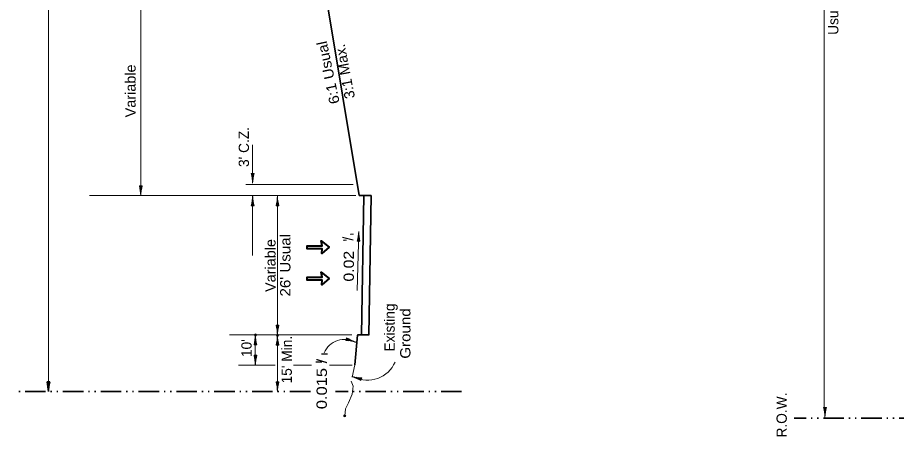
# Model space of a CAD drawing. Extents: x 2363427 to 2368559, y 6957299 to 6980140.
# Drawn here: x 2364654 to 2365851, y 6958010 to 6958581 of the extents above; entities that cross this region are included whole.
import ezdxf
from ezdxf.enums import TextEntityAlignment as Align

# ---------------------------------------------------------------- set-up
doc = ezdxf.new("R2010")
doc.units = 0
doc.header["$LTSCALE"] = 5.6
doc.header["$PDMODE"] = 32
doc.header["$PDSIZE"] = 2.8
doc.linetypes.add('DASH_DOUBLE_DOT', pattern=[9.2, 5, -1.2, 0.3, -1.2, 0.3, -1.2])
doc.linetypes.add('MEDIUM_DASHED', pattern=[4.5, 3, -1.5])
for name, color, linetype, lineweight in [('1', 7, 'Continuous', 13), ('3', 7, 'Continuous', 35), ('4', 7, 'Continuous', 13), ('40', 7, 'Continuous', 35), ('48', 7, 'Continuous', 25), ('6', 7, 'Continuous', 13), ('8', 7, 'Continuous', 13)]:
    doc.layers.add(name, color=color, linetype=linetype, lineweight=lineweight)

msp = doc.modelspace()

# ---------------------------------------------------------------- linework, layer by layer
at = {"layer": '1'}
for p, q in [((2365122.006, 6958088.321), (2365109.964, 6958091.909)), ((2365121.864, 6958087.843), (2365113.612, 6958090.301)), ((2365122.149, 6958088.801), (2365115.105, 6958090.899)), ((2365121.72, 6958087.363), (2365117.061, 6958088.751)), ((2365122.292, 6958089.28), (2365118.193, 6958090.501)), ((2365121.578, 6958086.884), (2365119.296, 6958087.564)), ((2365122.434, 6958089.759), (2365120.916, 6958090.211)), ((2365122.534, 6958090.095), (2365121.441, 6958086.424))]:
    msp.add_line(p, q, dxfattribs=at)
at = {"layer": '1', "linetype": 'MEDIUM_DASHED'}
msp.add_lwpolyline([(2365112.979, 6958107.766), (2365108.239, 6958085.654), (2365110.767, 6958078.9), (2365109.503, 6958068.094), (2365104.447, 6958055.936), (2365100.655, 6958047.83), (2365099.391, 6958038.374)], dxfattribs=at)
at = {"layer": '1'}
for centre, radius, start, end in [((2365130.612, 6958127.466), 40.455, 242.99828, 337.03823), ((2365085.206, 6958023.96), 72.212, 59.88222, 70.56827), ((2365126.387, 6958162.204), 72.212, 256.25538, 266.94143)]:
    msp.add_arc(centre, radius, start, end, dxfattribs=at)
msp.add_point((2365099.391, 6958038.374), dxfattribs=at)
at = {"layer": '3'}
for p, q in [((2365055.653, 6958721.475), (2365118.982, 6958338.693)), ((2365118.982, 6958338.693), (2365125.574, 6958338.663)), ((2365125.574, 6958338.663), (2365122.253, 6958148.629)), ((2365125.574, 6958338.663), (2365135.576, 6958338.755)), ((2365135.574, 6958338.622), (2365132.252, 6958148.542)), ((2365116.835, 6958148.531), (2365112.979, 6958107.766)), ((2365132.254, 6958148.629), (2365116.836, 6958148.629))]:
    msp.add_line(p, q, dxfattribs=at)
at = {"layer": '3', "lineweight": 13}
for p, q in [((2365110.704, 6958353.693), (2364964.692, 6958353.693)), ((2365114.719, 6958338.693), (2364751.658, 6958338.693)), ((2365116.266, 6958209.329), (2365118.542, 6958289.583)), ((2365117.23, 6958276.303), (2365117.368, 6958281.163)), ((2365117.73, 6958276.289), (2365117.974, 6958284.895)), ((2365118.229, 6958276.275), (2365118.586, 6958288.833)), ((2365118.729, 6958276.261), (2365118.938, 6958283.607)), ((2365119.229, 6958276.245), (2365119.35, 6958280.521)), ((2365120.078, 6958276.221), (2365116.25, 6958276.331)), ((2365116.73, 6958276.317), (2365116.798, 6958278.697)), ((2365119.728, 6958276.231), (2365119.774, 6958277.817)), ((2365109.097, 6958148.693), (2364942.34, 6958148.693)), ((2365116.835, 6958148.531), (2365116.836, 6958148.629))]:
    msp.add_line(p, q, dxfattribs=at)
at = {"layer": '3', "linetype": 'DASH_DOUBLE_DOT'}
for p, q in [((2365052.774, 6958071.447), (2364653.955, 6958071.447)), ((2365258.568, 6958071.447), (2365086.792, 6958071.447))]:
    msp.add_line(p, q, dxfattribs=at)
msp.add_lwpolyline([(2366112.816, 6958035.448), (2366088.198, 6958035.448), (2365711.269, 6958035.448)], dxfattribs=at)
at = {"layer": '3', "lineweight": 13}
for centre, start, end in [((2365046.548, 6958295.207), 344.84626, 355.53231), ((2365190.738, 6958291.119), 181.21943, 191.90548)]:
    msp.add_arc(centre, 72.212, start, end, dxfattribs=at)
at = {"layer": '4'}
for p, q in [((2365752.334, 6958047.045), (2365752.334, 6959081.469)), ((2364977.895, 6958135.176), (2364977.895, 6958147.74)), ((2364977.895, 6958135.176), (2364977.895, 6958147.74)), ((2364976.395, 6958135.176), (2364976.395, 6958137.558)), ((2364976.395, 6958135.176), (2364976.395, 6958137.558)), ((2364976.895, 6958135.176), (2364976.895, 6958140.038)), ((2364976.895, 6958135.176), (2364976.895, 6958140.038)), ((2364977.395, 6958135.176), (2364977.395, 6958143.786)), ((2364977.395, 6958135.176), (2364977.395, 6958143.786)), ((2364978.395, 6958135.176), (2364978.395, 6958142.526)), ((2364978.395, 6958135.176), (2364978.395, 6958142.526)), ((2364978.895, 6958135.176), (2364978.895, 6958139.453)), ((2364978.895, 6958135.176), (2364978.895, 6958139.453)), ((2364979.395, 6958135.176), (2364979.395, 6958136.762)), ((2364979.395, 6958135.176), (2364979.395, 6958136.762)), ((2365100.761, 6958141.274), (2365101.926, 6958144.923)), ((2365100.868, 6958141.607), (2365102.378, 6958141.125)), ((2365101.02, 6958142.084), (2365105.094, 6958140.783)), ((2365101.172, 6958142.56), (2365108.173, 6958140.323)), ((2365101.324, 6958143.037), (2365113.292, 6958139.213)), ((2365101.476, 6958143.513), (2365109.678, 6958140.893)), ((2365101.628, 6958143.989), (2365106.26, 6958142.509)), ((2365101.78, 6958144.465), (2365104.049, 6958143.741)), ((2364979.745, 6958135.176), (2364975.915, 6958135.176)), ((2364979.745, 6958135.176), (2364975.915, 6958135.176)), ((2364975.936, 6958120.983), (2364979.766, 6958120.983)), ((2364975.936, 6958120.983), (2364979.766, 6958120.983)), ((2364976.286, 6958120.983), (2364976.286, 6958119.399)), ((2364976.286, 6958120.983), (2364976.286, 6958119.399)), ((2364976.786, 6958120.983), (2364976.786, 6958116.707)), ((2364976.786, 6958120.983), (2364976.786, 6958116.707)), ((2364977.286, 6958120.983), (2364977.286, 6958113.633)), ((2364977.286, 6958120.983), (2364977.286, 6958113.633)), ((2364977.786, 6958120.983), (2364977.786, 6958108.419)), ((2364977.786, 6958120.983), (2364977.786, 6958108.419)), ((2364978.286, 6958120.983), (2364978.286, 6958112.374)), ((2364978.286, 6958120.983), (2364978.286, 6958112.374)), ((2364978.786, 6958120.983), (2364978.786, 6958116.121)), ((2364978.786, 6958120.983), (2364978.786, 6958116.121)), ((2364979.286, 6958120.983), (2364979.286, 6958118.602)), ((2364979.286, 6958120.983), (2364979.286, 6958118.602)), ((2365004.525, 6958107.585), (2364954.893, 6958107.585)), ((2365054.133, 6958107.585), (2365029.75, 6958107.585)), ((2365109.628, 6958107.585), (2365078.517, 6958107.585)), ((2365751.332, 6958049.826), (2365755.162, 6958049.826)), ((2365751.682, 6958049.826), (2365751.682, 6958048.241)), ((2365752.182, 6958049.826), (2365752.182, 6958045.549)), ((2365752.682, 6958049.826), (2365752.682, 6958042.476)), ((2365753.182, 6958049.826), (2365753.182, 6958037.262)), ((2365753.682, 6958049.826), (2365753.682, 6958041.217)), ((2365754.182, 6958049.826), (2365754.182, 6958044.964)), ((2365754.682, 6958049.826), (2365754.682, 6958047.445))]:
    msp.add_line(p, q, dxfattribs=at)
at = {"layer": '4', "lineweight": 25}
for p, q in [((2365068.431, 6958111.524), (2365060.271, 6958111.524)), ((2365075.749, 6958122.347), (2365067.588, 6958122.347))]:
    msp.add_line(p, q, dxfattribs=at)
at = {"layer": '4', "lineweight": 35}
for p, q in [((2364694.018, 6958084.759), (2364697.848, 6958084.759)), ((2364694.368, 6958084.759), (2364694.368, 6958083.173)), ((2364694.868, 6958084.759), (2364694.868, 6958080.481)), ((2364695.368, 6958084.759), (2364695.368, 6958077.409)), ((2364695.868, 6958084.759), (2364695.868, 6958072.195)), ((2364696.368, 6958084.759), (2364696.368, 6958076.149)), ((2364696.868, 6958084.759), (2364696.868, 6958079.897)), ((2364697.368, 6958084.759), (2364697.368, 6958082.377))]:
    msp.add_line(p, q, dxfattribs=at)
at = {"layer": '4'}
for centre, radius, start, end in [((2364905.707, 6958152.069), 72.212, 346.47039, 357.15644), ((2364905.707, 6958152.069), 72.212, 346.47039, 357.15644), ((2365049.954, 6958152.069), 72.212, 182.84356, 193.52961), ((2365049.954, 6958152.069), 72.212, 182.84356, 193.52961), ((2365099.004, 6958112.983), 29.635, 59.62074, 157.81619), ((2365095.488, 6958069.253), 72.212, 75.12659, 85.81264), ((2365139.385, 6958206.658), 72.212, 238.75343, 249.43948), ((2364905.728, 6958104.088), 72.212, 2.84356, 13.52961), ((2364905.728, 6958104.088), 72.212, 2.84356, 13.52961), ((2365049.975, 6958104.088), 72.212, 166.47039, 177.15644), ((2365049.975, 6958104.088), 72.212, 166.47039, 177.15644), ((2365681.124, 6958032.932), 72.212, 2.84356, 13.52961), ((2365825.371, 6958032.932), 72.212, 166.47039, 177.15644)]:
    msp.add_arc(centre, radius, start, end, dxfattribs=at)
at = {"layer": '4', "lineweight": 35}
for centre, start, end in [((2364623.81, 6958067.864), 2.84356, 13.52961), ((2364768.057, 6958067.864), 166.47039, 177.15644)]:
    msp.add_arc(centre, 72.212, start, end, dxfattribs=at)
at = {"layer": '4'}
for p in [(2364977.831, 6958148.889), (2364977.831, 6958148.488)]:
    msp.add_point(p, dxfattribs=at)
at = {"layer": '40'}
for p, q in [((2365068.578, 6958266.155), (2365048.073, 6958265.959)), ((2365068.578, 6958223.336), (2365048.073, 6958223.141))]:
    msp.add_line(p, q, dxfattribs=at)
for points in [[(2365068.54, 6958270.249), (2365048.036, 6958270.055), (2365048.073, 6958265.959)], [(2365068.578, 6958266.155), (2365068.046, 6958259.839), (2365078.433, 6958268.375), (2365067.333, 6958276.977), (2365068.54, 6958270.249)], [(2365068.578, 6958223.336), (2365068.046, 6958217.021), (2365078.433, 6958225.556), (2365067.333, 6958234.159), (2365068.54, 6958227.431)], [(2365068.54, 6958227.431), (2365048.036, 6958227.236), (2365048.073, 6958223.141)]]:
    msp.add_lwpolyline(points, dxfattribs=at)
at = {"layer": '48', "lineweight": 13}
msp.add_lwpolyline([(2365122.253, 6958148.629), (2365132.252, 6958148.542), (2365135.574, 6958338.622), (2365125.574, 6958338.663)], close=True, dxfattribs=at)
at = {"layer": '6'}
for p, q in [((2364695.934, 6958071.447), (2364695.934, 6959071.447)), ((2364821.74, 6958619.485), (2364821.74, 6958338.693)), ((2364973.994, 6958355.333), (2364973.994, 6958407.695)), ((2364972.08, 6958368.645), (2364975.91, 6958368.645)), ((2364972.43, 6958368.645), (2364972.43, 6958367.061)), ((2364972.93, 6958368.645), (2364972.93, 6958364.369)), ((2364973.43, 6958368.645), (2364973.43, 6958361.295)), ((2364973.93, 6958368.645), (2364973.93, 6958356.081)), ((2364974.43, 6958368.645), (2364974.43, 6958360.035)), ((2364974.93, 6958368.645), (2364974.93, 6958363.783)), ((2364975.43, 6958368.645), (2364975.43, 6958366.263)), ((2364819.825, 6958352.003), (2364823.655, 6958352.003)), ((2364820.175, 6958352.003), (2364820.175, 6958350.419)), ((2364820.675, 6958352.003), (2364820.675, 6958347.727)), ((2364821.175, 6958352.003), (2364821.175, 6958344.653)), ((2364821.675, 6958352.003), (2364821.675, 6958339.439)), ((2364822.175, 6958352.003), (2364822.175, 6958343.395)), ((2364822.675, 6958352.003), (2364822.675, 6958347.141)), ((2364823.175, 6958352.003), (2364823.175, 6958349.623)), ((2364972.56, 6958324.567), (2364972.56, 6958326.949)), ((2364973.06, 6958324.567), (2364973.06, 6958329.429)), ((2364973.56, 6958324.567), (2364973.56, 6958333.177)), ((2364973.994, 6958337.879), (2364973.994, 6958256.743)), ((2364974.06, 6958324.567), (2364974.06, 6958337.131)), ((2364974.56, 6958324.567), (2364974.56, 6958331.917)), ((2364975.06, 6958324.567), (2364975.06, 6958328.845)), ((2365006.396, 6958324.567), (2365006.396, 6958326.949)), ((2365006.896, 6958324.567), (2365006.896, 6958329.429)), ((2365007.396, 6958324.567), (2365007.396, 6958333.177)), ((2365007.83, 6958337.879), (2365007.83, 6958148.693)), ((2365007.896, 6958324.567), (2365007.896, 6958337.131)), ((2365008.396, 6958324.567), (2365008.396, 6958331.917)), ((2365008.896, 6958324.567), (2365008.896, 6958328.845)), ((2364975.91, 6958324.567), (2364972.08, 6958324.567)), ((2364975.56, 6958324.567), (2364975.56, 6958326.153)), ((2365009.746, 6958324.567), (2365005.916, 6958324.567)), ((2365009.396, 6958324.567), (2365009.396, 6958326.153)), ((2365005.916, 6958162.003), (2365009.746, 6958162.003)), ((2365006.266, 6958162.003), (2365006.266, 6958160.419)), ((2365006.766, 6958162.003), (2365006.766, 6958157.727)), ((2365007.266, 6958162.003), (2365007.266, 6958154.653)), ((2365007.766, 6958162.003), (2365007.766, 6958149.439)), ((2365008.266, 6958162.003), (2365008.266, 6958153.395)), ((2365008.766, 6958162.003), (2365008.766, 6958157.141)), ((2365009.266, 6958162.003), (2365009.266, 6958159.623)), ((2364977.56, 6958148.487), (2364977.56, 6958107.585)), ((2365007.83, 6958148.067), (2365007.83, 6958071.447)), ((2365006.396, 6958134.755), (2365006.396, 6958137.137)), ((2365006.896, 6958134.755), (2365006.896, 6958139.617)), ((2365007.396, 6958134.755), (2365007.396, 6958143.365)), ((2365007.896, 6958134.755), (2365007.896, 6958147.319)), ((2365008.396, 6958134.755), (2365008.396, 6958142.105)), ((2365008.896, 6958134.755), (2365008.896, 6958139.033)), ((2365009.396, 6958134.755), (2365009.396, 6958136.341)), ((2365009.746, 6958134.755), (2365005.916, 6958134.755)), ((2365005.916, 6958084.759), (2365009.746, 6958084.759)), ((2365006.266, 6958084.759), (2365006.266, 6958083.173)), ((2365006.766, 6958084.759), (2365006.766, 6958080.481)), ((2365007.266, 6958084.759), (2365007.266, 6958077.409)), ((2365007.766, 6958084.759), (2365007.766, 6958072.195)), ((2365008.266, 6958084.759), (2365008.266, 6958076.149)), ((2365008.766, 6958084.759), (2365008.766, 6958079.897)), ((2365009.266, 6958084.759), (2365009.266, 6958082.377))]:
    msp.add_line(p, q, dxfattribs=at)
for centre, start, end in [((2364901.871, 6958351.751), 2.84356, 13.52961), ((2365046.118, 6958351.751), 166.47039, 177.15644), ((2364749.616, 6958335.11), 2.84356, 13.52961), ((2364893.864, 6958335.11), 166.47039, 177.15644), ((2364901.871, 6958341.462), 346.47039, 357.15644), ((2365046.118, 6958341.462), 182.84356, 193.52961), ((2364935.707, 6958341.462), 346.47039, 357.15644), ((2365079.954, 6958341.462), 182.84356, 193.52961), ((2364935.707, 6958145.11), 2.84356, 13.52961), ((2365079.954, 6958145.11), 166.47039, 177.15644), ((2364935.707, 6958151.65), 346.47039, 357.15644), ((2365079.954, 6958151.65), 182.84356, 193.52961), ((2364935.707, 6958067.864), 2.84356, 13.52961), ((2365079.954, 6958067.864), 166.47039, 177.15644)]:
    msp.add_arc(centre, 72.212, start, end, dxfattribs=at)
msp.add_point((2365007.83, 6958148.067), dxfattribs=at)
at = {"layer": '8', "lineweight": 40}
for points in [[(2365078.433, 6958268.375), (2365068.046, 6958259.839), (2365068.578, 6958266.155), (2365048.073, 6958265.959), (2365048.036, 6958270.055), (2365068.54, 6958270.249), (2365067.333, 6958276.977)], [(2365078.433, 6958225.556), (2365068.046, 6958217.021), (2365068.578, 6958223.336), (2365048.073, 6958223.141), (2365048.036, 6958227.236), (2365068.54, 6958227.431), (2365067.333, 6958234.159)]]:
    msp.add_lwpolyline(points, close=True, dxfattribs=at)

# ---------------------------------------------------------------- texts
at = {"layer": '4'}
for s, p in [('Usual min.', (2365771.551, 6958601.81)), ("3' C.Z.", (2364969.011, 6958404.792)), ('/', (2365110.75, 6958279.891)), ("'", (2365120.951, 6958285.865)), ("'", (2365111.478, 6958277.678)), ('Existing ', (2365167.468, 6958161.424)), ("10' ", (2364972.661, 6958133.271)), ("15' Min.", (2365027.414, 6958115.006)), ('R.O.W.', (2365701.308, 6958039.487))]:
    msp.add_text(s, height=14, rotation=90, dxfattribs=at).set_placement(p, align=Align.CENTER)
for s, rotation, width, p in [('6:1 Usual', 101.975, 1.1, (2365083.706, 6958507.614)), ('3:1 Max.', 100.991, 1.05, (2365106.352, 6958508.973)), ('Variable', 90, 1.05, (2364814.706, 6958481.195)), ("26' Usual", 90, 1.1, (2365025.478, 6958243.614)), ('Variable', 90, 1.05, (2365005.15, 6958243.259)), ('0.02', 90, 1.15, (2365111.888, 6958242.332)), ('Ground', 90, 1.1, (2365188.878, 6958150.623)), ('0.015 /', 89.708, 1.2, (2365075.109, 6958081.778))]:
    msp.add_text(s, height=14, rotation=rotation, dxfattribs=dict(at, width=width)).set_placement(p, align=Align.CENTER)

doc.saveas('drawing.dxf')
